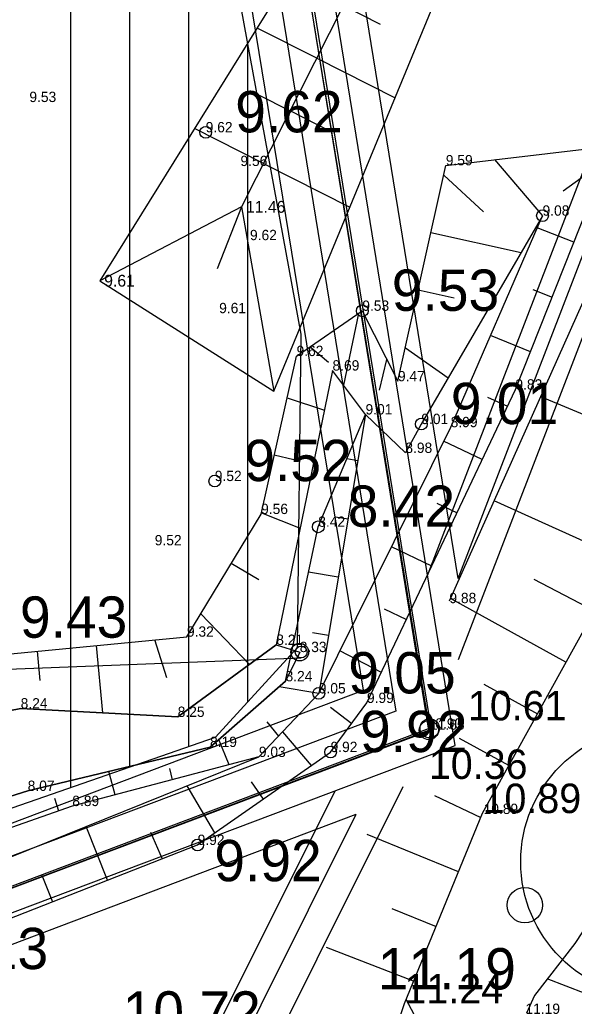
# Model space of a CAD drawing. Extents: x 433497 to 434382, y 6534486 to 6534993.
# Drawn here: x 434123.48 to 434142.29, y 6534787.09 to 6534820.55 of the extents above; entities that cross this region are included whole.
import ezdxf

# ---------------------------------------------------------------- set-up
doc = ezdxf.new("R2010")
doc.units = 0
for name, color, linetype in [('Default', 7, 'Continuous'), ('HALJASTUS', 7, 'Continuous'), ('kataster', 7, 'Continuous'), ('KORGUS-EH2000', 7, 'Continuous'), ('MAAMUDEL-EH2000', 7, 'Continuous'), ('MOOTKORG-EH2000', 7, 'Continuous'), ('PIIR', 7, 'Continuous'), ('RELJEEF', 7, 'Continuous'), ('Täide', 7, 'Continuous'), ('VEEKOGU', 7, 'Continuous')]:
    doc.layers.add(name, color=color, linetype=linetype)

msp = doc.modelspace()

# ---------------------------------------------------------------- linework, layer by layer
at = {"layer": 'Default'}
msp.add_lwpolyline([(433617.12, 6534791.025), (433632.75, 6534606.045), (434137.38, 6534796.515), (434127.69, 6534855.6), (433968.21, 6534911.925), (433942.38, 6534904.035), (433920.99, 6534907.275)], close=True, dxfattribs=at)
msp.add_lwpolyline([(433617.12, 6534791.025), (433632.75, 6534606.045), (434137.38, 6534796.515), (434127.69, 6534855.6), (433968.21, 6534911.925), (433942.38, 6534904.035), (433920.99, 6534907.275)], close=True, dxfattribs=at)
msp.add_lwpolyline([(433617.12, 6534791.025), (433632.75, 6534606.045), (434137.38, 6534796.515), (434127.69, 6534855.6), (433968.21, 6534911.925), (433942.38, 6534904.035), (433920.99, 6534907.275)], close=True, dxfattribs=at)
at = {"layer": 'HALJASTUS'}
msp.add_circle((434140.609, 6534790.519), 0.6, dxfattribs=at)
at = {"layer": 'kataster'}
msp.add_lwpolyline([(433617.102, 6534791.002), (433632.769, 6534606.029), (434137.446, 6534796.469), (434127.827, 6534855.589), (433950.026, 6534918.39)], close=True, dxfattribs=at)
at = {"layer": 'KORGUS-EH2000'}
for centre in [(434129.784, 6534816.727), (434141.209, 6534813.9), (434135.095, 6534810.674), (434137.097, 6534806.833), (434130.093, 6534804.9), (434133.601, 6534803.349), (434133.62, 6534797.699), (434134.019, 6534795.71), (434129.51, 6534792.559)]:
    msp.add_circle(centre, 0.2, dxfattribs=at)
at = {"layer": 'PIIR'}
for points in [[(434138.342, 6534801.592), (434129.36, 6534856.88), (433968.248, 6534913.871)], [(433632.021, 6534604.835), (434138.248, 6534795.936), (434128.468, 6534856.135), (433968.226, 6534912.818), (433942.33, 6534904.85), (433920.952, 6534908.165), (433616.327, 6534791.524), (433632.021, 6534604.835)], [(433632.732, 6534605.959), (434137.353, 6534796.454), (434127.754, 6534855.539), (433968.208, 6534911.976), (433942.39, 6534904.031), (433921.04, 6534907.341), (433617.174, 6534790.992), (433632.732, 6534605.959)], [(434137.312, 6534801.699), (434156.44, 6534851.34), (434184.392, 6534902.877)], [(434138.342, 6534801.592), (434157.35, 6534850.92), (434185.271, 6534902.4)], [(434138.358, 6534798.853), (434158.26, 6534850.5), (434186.15, 6534901.923)], [(434096.984, 6534713.464), (434111.196, 6534747.086), (434125.923, 6534777.863), (434134.171, 6534794.397)], [(434098.826, 6534712.686), (434113.02, 6534746.265), (434127.72, 6534776.985), (434136.477, 6534794.54)], [(433633.446, 6534604.304), (434134.891, 6534793.6)], [(434097.905, 6534713.075), (434112.108, 6534746.676), (434126.821, 6534777.424), (434134.891, 6534793.6)]]:
    msp.add_lwpolyline(points, dxfattribs=at)
for points in [[(433618.234, 6534790.327), (433921.149, 6534906.313), (433942.464, 6534903.008), (433968.187, 6534910.923), (434126.862, 6534854.794), (434136.235, 6534797.101), (433633.617, 6534607.362)], [(433619.24, 6534789.695), (433634.52, 6534608.851), (434135.141, 6534797.808), (434125.908, 6534854.108), (433968.165, 6534909.82), (433942.53, 6534901.99), (433921.212, 6534905.219)], [(433619.24, 6534789.695), (433634.52, 6534608.851), (434135.141, 6534797.808), (434125.908, 6534854.108), (433968.165, 6534909.82), (433942.53, 6534901.99), (433921.212, 6534905.219)]]:
    msp.add_lwpolyline(points, close=True, dxfattribs=at)
for centre, radius in [((434137.353, 6534796.454), 0.325), ((434137.38, 6534796.515), 0.325), ((434145.069, 6534791.991), 4.6)]:
    msp.add_circle(centre, radius, dxfattribs=at)
at = {"layer": 'RELJEEF'}
for p, q in [((434135.711, 6534820.387), (434134.45, 6534821.025)), ((434133.548, 6534819.24), (434131.526, 6534820.262)), ((434133.548, 6534819.24), (434136.207, 6534817.896)), ((434131.555, 6534818.006), (434132.645, 6534817.455)), ((434134.043, 6534816.748), (434132.645, 6534817.455)), ((434131.743, 6534815.67), (434129.404, 6534816.853)), ((434139.582, 6534815.801), (434141.209, 6534813.9)), ((434131.743, 6534815.67), (434134.676, 6534814.188)), ((434143.26, 6534815.713), (434141.911, 6534814.734)), ((434139.205, 6534814.028), (434137.856, 6534815.28)), ((434131, 6534814.2), (434126.192, 6534811.695)), ((434131, 6534814.2), (434130.17, 6534812.102)), ((434131, 6534814.2), (434132.1, 6534807.95)), ((434142.274, 6534813.001), (434141.032, 6534813.493)), ((434137.423, 6534813.328), (434140.481, 6534812.649)), ((434138.208, 6534811.105), (434136.99, 6534811.375)), ((434140.885, 6534811.4), (434141.535, 6534811.142)), ((434134.967, 6534810.586), (434134.455, 6534808.156)), ((434140.797, 6534809.283), (434139.443, 6534809.836)), ((434133.953, 6534808.925), (434133.32, 6534809.452)), ((434136.557, 6534809.423), (434138.008, 6534808.399)), ((434135.684, 6534807.98), (434135.928, 6534809.028)), ((434132.549, 6534807.726), (434133.81, 6534807.307)), ((434139.344, 6534807.743), (434140.022, 6534807.44)), ((434145.388, 6534805.988), (434141.148, 6534807.761)), ((434135.205, 6534807.159), (434133.62, 6534797.699)), ((434135.205, 6534807.159), (434135.205, 6534807.159)), ((434139.166, 6534805.633), (434137.849, 6534806.257)), ((434132.773, 6534805.626), (434132.111, 6534805.774)), ((434134.942, 6534805.589), (434134.57, 6534805.651)), ((434137.619, 6534804.153), (434138.31, 6534803.825)), ((434143.845, 6534802.298), (434139.569, 6534804.231)), ((434131.673, 6534803.823), (434132.988, 6534803.299)), ((434134.192, 6534803.687), (434134.611, 6534803.617)), ((434137.453, 6534802.018), (434136.082, 6534802.668)), ((434131.582, 6534801.547), (434130.651, 6534802.106)), ((434134.281, 6534801.644), (434133.276, 6534801.812)), ((434140.914, 6534801.571), (434142.97, 6534800.503)), ((434142.002, 6534798.753), (434138.087, 6534800.918)), ((434129.616, 6534800.395), (434131.274, 6534798.685)), ((434135.842, 6534800.568), (434136.597, 6534800.211)), ((434133.406, 6534799.763), (434133.95, 6534799.672)), ((434126.066, 6534799.324), (434126.287, 6534797.039)), ((434128.464, 6534798.223), (434128.057, 6534799.516)), ((434124.171, 6534798.139), (434124.075, 6534799.132)), ((434135.741, 6534798.403), (434134.335, 6534799.143)), ((434139.217, 6534798.008), (434141.034, 6534797.002)), ((434133.62, 6534797.699), (434132.278, 6534797.924)), ((434133.62, 6534797.699), (434132.278, 6534797.924)), ((434134.014, 6534797.229), (434134.74, 6534796.682)), ((434131.86, 6534796.733), (434132.248, 6534796.244)), ((434133.372, 6534795.258), (434132.395, 6534796.4)), ((434130.584, 6534795.279), (434130.229, 6534796.14)), ((434140.066, 6534795.252), (434138.395, 6534796.167)), ((434126.716, 6534794.261), (434126.499, 6534795.055)), ((434128.551, 6534795.148), (434128.65, 6534794.77)), ((434131.323, 6534794.698), (434131.732, 6534794.112)), ((434130.093, 6534792.966), (434129.151, 6534794.562)), ((434124.656, 6534794.146), (434124.794, 6534793.714)), ((434137.546, 6534794.238), (434139.114, 6534793.494)), ((434126.448, 6534791.36), (434125.732, 6534793.19)), ((434127.91, 6534792.998), (434128.31, 6534792.089)), ((434138.355, 6534791.644), (434135.259, 6534792.914)), ((434124.231, 6534791.537), (434124.585, 6534790.631)), ((434136.098, 6534790.408), (434137.596, 6534789.794)), ((434136.837, 6534787.943), (434133.877, 6534789.085)), ((434142.65, 6534787.517), (434141.37, 6534788.014)), ((434139.86, 6534781.218), (434136.58, 6534787.318))]:
    msp.add_line(p, q, dxfattribs=at)
for points in [[(434126.192, 6534811.695), (434132.1, 6534807.95), (434137.84, 6534821.85), (434145.35, 6534843.91), (434148.595, 6534858.023), (434153.175, 6534872.071), (434151.226, 6534875.962), (434145.88, 6534874.56)], [(434145.88, 6534874.56), (434139.435, 6534859.319), (434137.93, 6534846.04), (434135.82, 6534833.16), (434132.11, 6534821.2), (434126.192, 6534811.695)], [(434147.81, 6534873.14), (434142.66, 6534853), (434140.649, 6534839.695), (434136.95, 6534825.97), (434131, 6534814.2)], [(434113.19, 6534781.228), (434119.148, 6534781.228), (434129.078, 6534780.4), (434131.196, 6534780.65), (434133.547, 6534781.228), (434134.6, 6534782.717), (434135.868, 6534785.182), (434136.526, 6534787.186), (434139.174, 6534793.64), (434143.477, 6534801.419), (434147.284, 6534810.522), (434153.573, 6534824.093), (434156.717, 6534837.003), (434157.71, 6534847.595)], [(434158.687, 6534827.511), (434156.433, 6534820.225), (434154.235, 6534815.156), (434152.292, 6534810.738), (434149.27, 6534804.895), (434147.653, 6534802.794), (434145.688, 6534800.671), (434144.636, 6534798.937), (434144.063, 6534796.557), (434143.906, 6534793.097), (434143.312, 6534790.827), (434142.844, 6534790.044), (434142.307, 6534789.219), (434140.931, 6534787.45), (434140.664, 6534786.855)], [(434138.05, 6534800.835), (434147.118, 6534821.114), (434146.988, 6534822.533)], [(434108.205, 6534793.713), (434116.351, 6534796.246), (434120.106, 6534798.748), (434129.148, 6534799.622), (434131.664, 6534803.782), (434132.866, 6534809.14), (434135.095, 6534810.674), (434136.304, 6534808.284), (434137.928, 6534815.607), (434143.009, 6534816.202), (434143.311, 6534815.613)], [(434109.687, 6534786.673), (434112.222, 6534786.179), (434118.757, 6534788.35), (434129.51, 6534792.559), (434134.019, 6534795.71), (434135.253, 6534797.374), (434140.289, 6534808.003), (434143.311, 6534815.613)], [(434109.687, 6534786.673), (434117.282, 6534789.783), (434131.587, 6534795.543), (434133.62, 6534797.699), (434138.093, 6534806.728), (434141.209, 6534813.9)], [(434141.209, 6534813.9), (434137.097, 6534806.833), (434136.556, 6534805.855), (434135.205, 6534807.159), (434134.085, 6534808.648), (434132.177, 6534799.345), (434128.834, 6534796.902), (434123.508, 6534797.188), (434120.837, 6534796.664), (434109.765, 6534791.743), (434109.765, 6534791.743), (434110.035, 6534790.072)], [(434110.035, 6534790.072), (434110.035, 6534790.072), (434110.035, 6534790.072), (434123.746, 6534794.392), (434129.931, 6534795.881), (434132.492, 6534798.11), (434133.601, 6534803.349), (434135.205, 6534807.159)], [(434133.62, 6534797.699), (434131.587, 6534795.543), (434125.259, 6534793.878), (434114.603, 6534790.134), (434109.687, 6534786.673), (434109.111, 6534789.39), (434108.205, 6534793.713)]]:
    msp.add_lwpolyline(points, dxfattribs=at)
at = {"layer": 'Täide'}
for p, q in [((434125.213, 6534794.516), (434125.213, 6534852.38)), ((434127.213, 6534795.211), (434127.213, 6534841.489)), ((434129.213, 6534795.906), (434129.213, 6534830.597)), ((434131.213, 6534797.418), (434131.213, 6534819.705))]:
    msp.add_line(p, q, dxfattribs=at)
msp.add_lwpolyline([(434053.953, 6534766.741), (434062.043, 6534770.897), (434076.601, 6534775.79), (434083.107, 6534779.636), (434100.67, 6534785.732), (434110.817, 6534789.511), (434130.115, 6534796.22), (434132.899, 6534799.258), (434133.017, 6534809.88), (434125.182, 6534852.548), (434123.278, 6534854.722), (434098.113, 6534862.108), (434062.901, 6534875.407), (434022.093, 6534888.443), (434021.059, 6534887.256), (434037.893, 6534864.165), (434021.392, 6534791.18), (434023.3, 6534781.148), (434025.663, 6534773.898), (434039.607, 6534770.357), (434045.083, 6534767.989), (434045.714, 6534765.502), (434044.882, 6534761.539)], dxfattribs=at)
at = {"layer": 'VEEKOGU'}
msp.add_lwpolyline([(434110.035, 6534790.072), (434109.765, 6534791.743), (434120.837, 6534796.664), (434123.508, 6534797.188), (434128.834, 6534796.902), (434132.177, 6534799.345), (434132.972, 6534799.1), (434132.492, 6534798.11), (434129.931, 6534795.881), (434123.746, 6534794.392)], close=True, dxfattribs=at)
msp.add_lwpolyline([(434101.202, 6534798.262), (434116.33, 6534798.262), (434133.022, 6534798.9)], dxfattribs=at)
for centre, radius in [((434132.972, 6534799.1), 0.3), ((434133.022, 6534799.1), 0.2)]:
    msp.add_circle(centre, radius, dxfattribs=at)

# ---------------------------------------------------------------- texts
at = {"layer": 'KORGUS-EH2000'}
for s, p in [('9.62', (434130.784, 6534816.727)), ('9.53', (434136.095, 6534810.674)), ('9.01', (434138.097, 6534806.833)), ('9.52', (434131.093, 6534804.9)), ('8.42', (434134.601, 6534803.349)), ('9.43', (434123.482, 6534799.588)), ('9.05', (434134.62, 6534797.699)), ('9.92', (434135.019, 6534795.71)), ('9.92', (434130.075, 6534791.331)), ('10.13', (434119.757, 6534788.35)), ('11.19', (434135.62, 6534787.66)), ('10.72', (434126.966, 6534786.195))]:
    msp.add_text(s, height=1.4, dxfattribs=at).set_placement(p)
at = {"layer": 'MAAMUDEL-EH2000'}
for s, p in [(' 11.46', (434131, 6534814)), (' 9.61', (434126.192, 6534811.495))]:
    msp.add_text(s, height=0.4, dxfattribs=at).set_placement(p)
at = {"layer": 'MOOTKORG-EH2000'}
for s, height, p in [('9.53', 0.35, (434123.803, 6534817.754)), ('9.62', 0.35, (434129.784, 6534816.727)), ('9.56', 0.35, (434130.963, 6534815.584)), ('9.59', 0.35, (434137.928, 6534815.607)), ('9.08', 0.35, (434141.209, 6534813.9)), ('9.62', 0.35, (434131.286, 6534813.07)), ('9.61', 0.35, (434130.241, 6534810.594)), ('9.53', 0.35, (434135.095, 6534810.674)), ('9.62', 0.35, (434132.866, 6534809.14)), ('8.69', 0.35, (434134.085, 6534808.648)), ('9.47', 0.35, (434136.304, 6534808.284)), ('9.83', 0.35, (434140.289, 6534808.003)), ('9.01', 0.35, (434135.205, 6534807.159)), ('9.01', 0.35, (434137.097, 6534806.833)), ('8.99', 0.35, (434138.093, 6534806.728)), ('8.98', 0.35, (434136.556, 6534805.855)), ('9.52', 0.35, (434130.093, 6534804.9)), ('9.56', 0.35, (434131.664, 6534803.782)), ('8.42', 0.35, (434133.601, 6534803.349)), ('9.52', 0.35, (434128.056, 6534802.721)), ('9.88', 0.35, (434138.05, 6534800.76)), ('9.32', 0.35, (434129.148, 6534799.622)), ('8.21', 0.35, (434132.177, 6534799.345)), ('8.33', 0.35, (434132.972, 6534799.1)), ('8.24', 0.35, (434132.492, 6534798.11)), ('9.05', 0.35, (434133.62, 6534797.699)), ('9.99', 0.35, (434135.253, 6534797.374)), ('10.61', 1, (434138.678, 6534796.785)), ('8.24', 0.35, (434123.508, 6534797.188)), ('8.25', 0.35, (434128.834, 6534796.902)), ('10.90', 0.35, (434137.311, 6534796.505)), ('11.65', 0.35, (434137.392, 6534796.465)), ('8.19', 0.35, (434129.931, 6534795.881)), ('9.92', 0.35, (434134.019, 6534795.71)), ('9.03', 0.35, (434131.587, 6534795.543)), ('10.36', 1, (434137.353, 6534794.799)), ('8.07', 0.35, (434123.746, 6534794.392)), ('10.89', 1, (434139.174, 6534793.64)), ('8.89', 0.35, (434125.259, 6534793.878)), ('10.89', 0.35, (434139.21, 6534793.61)), ('9.92', 0.35, (434129.51, 6534792.559)), ('11.24', 1, (434136.526, 6534787.186)), ('11.19', 0.35, (434140.63, 6534786.83))]:
    msp.add_text(s, height=height, dxfattribs=at).set_placement(p)

doc.saveas('drawing.dxf')
